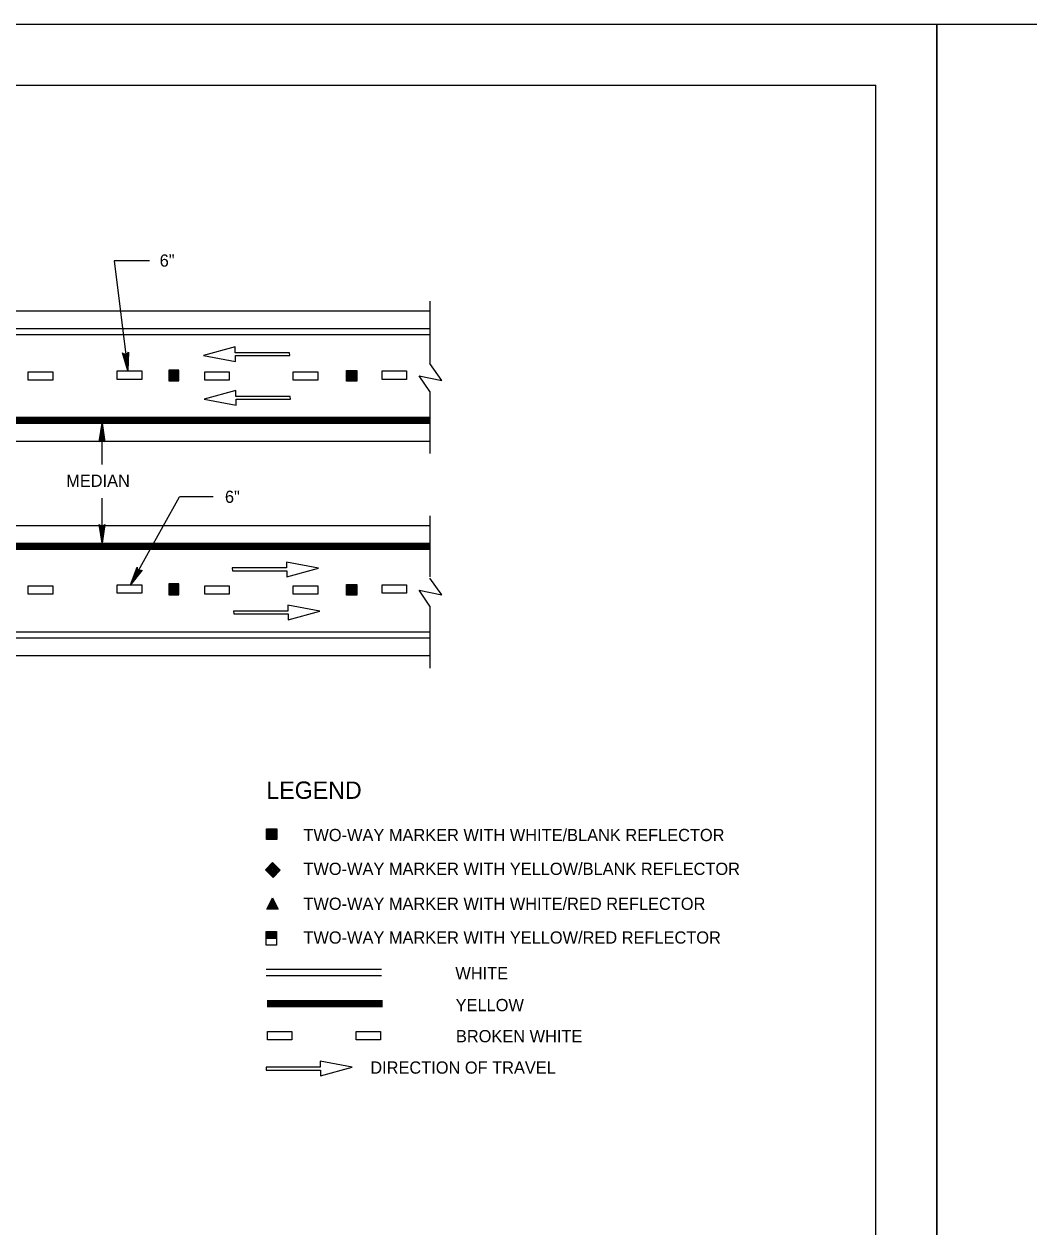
# Model space of a CAD drawing. Extents: x 639362 to 641108, y 298458 to 299646.
# Drawn here: x 639979.6 to 640225.9, y 299350.7 to 299645.6 of the extents above; entities that cross this region are included whole.
import ezdxf

# ---------------------------------------------------------------- set-up
doc = ezdxf.new("R2010")
doc.units = 0
for name, color, linetype in [('1', 7, 'Continuous'), ('2', 7, 'Continuous'), ('PLT-BNDY', 7, 'Continuous')]:
    doc.layers.add(name, color=color, linetype=linetype)

msp = doc.modelspace()

# ---------------------------------------------------------------- linework, layer by layer
at = {"layer": '1'}
for p in [(639402.31, 299630.63), (640188.31, 299066.63)]:
    msp.add_line(p, (640188.31, 299630.63), dxfattribs=at)
at = {"layer": '2'}
for p, q in [((640001.7, 299587.59), (640004.99, 299560.58)), ((640010.32, 299587.59), (640001.7, 299587.59)), ((640078.99, 299577.68), (640078.99, 299562.41)), ((639844.48, 299575.33), (640078.99, 299575.33)), ((639844.48, 299570.98), (640078.99, 299570.98)), ((639844.48, 299569.48), (640078.99, 299569.48)), ((640031.32, 299566.5), (640023.59, 299564.39)), ((640023.59, 299564.39), (640031.4, 299562.91)), ((640031.32, 299565.06), (640031.32, 299566.5)), ((640044.64, 299565.06), (640031.32, 299565.06)), ((640031.4, 299562.91), (640031.4, 299564.35)), ((640031.4, 299564.35), (640044.72, 299564.35)), ((640044.72, 299564.39), (640044.64, 299565.06)), ((640044.72, 299564.35), (640044.72, 299564.39)), ((640081.94, 299558.27), (640078.99, 299562.41)), ((639980.6, 299558.33), (639980.6, 299560.39)), ((639980.6, 299560.39), (639986.61, 299560.39)), ((639986.61, 299558.33), (639980.6, 299558.33)), ((639986.61, 299560.39), (639986.61, 299558.33)), ((640002.41, 299558.51), (640002.41, 299560.58)), ((640002.41, 299560.58), (640008.42, 299560.58)), ((640008.42, 299558.51), (640002.41, 299558.51)), ((640008.42, 299560.58), (640008.42, 299558.51)), ((640017.55, 299560.81), (640015.05, 299560.81)), ((640015.05, 299560.81), (640015.05, 299558.16)), ((640015.05, 299558.16), (640017.55, 299558.16)), ((640017.36, 299560.68), (640015.23, 299560.68)), ((640015.23, 299560.68), (640015.23, 299558.29)), ((640015.23, 299558.29), (640017.36, 299558.29)), ((640017.18, 299560.51), (640015.41, 299560.51)), ((640015.41, 299560.51), (640015.41, 299558.47)), ((640015.41, 299558.47), (640017.18, 299558.47)), ((640017, 299560.33), (640015.59, 299560.33)), ((640015.59, 299560.33), (640015.59, 299558.64)), ((640015.59, 299558.64), (640017, 299558.64)), ((640016.83, 299560.15), (640015.76, 299560.15)), ((640015.76, 299560.15), (640015.76, 299558.82)), ((640015.76, 299558.82), (640016.83, 299558.82)), ((640015.94, 299559.97), (640015.94, 299559)), ((640016.65, 299559.97), (640015.94, 299559.97)), ((640015.94, 299559), (640016.65, 299559)), ((640016.47, 299559.79), (640016.12, 299559.79)), ((640016.12, 299559.79), (640016.12, 299559.17)), ((640016.12, 299559.17), (640016.47, 299559.17)), ((640016.3, 299559.62), (640016.3, 299559.35)), ((640016.47, 299559.17), (640016.47, 299559.79)), ((640016.65, 299559), (640016.65, 299559.97)), ((640016.83, 299558.82), (640016.83, 299560.15)), ((640017, 299558.64), (640017, 299560.33)), ((640017.18, 299558.47), (640017.18, 299560.51)), ((640017.36, 299558.29), (640017.36, 299560.68)), ((640017.55, 299558.16), (640017.55, 299560.81)), ((640023.86, 299558.33), (640023.86, 299560.39)), ((640023.86, 299560.39), (640029.87, 299560.39)), ((640029.87, 299558.33), (640023.86, 299558.33)), ((640029.87, 299560.39), (640029.87, 299558.33)), ((640045.56, 299558.33), (640045.56, 299560.39)), ((640045.56, 299560.39), (640051.57, 299560.39)), ((640051.57, 299558.33), (640045.56, 299558.33)), ((640051.57, 299560.39), (640051.57, 299558.33)), ((640058.61, 299560.69), (640061.1, 299560.69)), ((640058.61, 299558.04), (640058.61, 299560.69)), ((640061.1, 299558.04), (640058.61, 299558.04)), ((640058.79, 299560.56), (640060.92, 299560.56)), ((640058.79, 299558.17), (640058.79, 299560.56)), ((640060.92, 299558.17), (640058.79, 299558.17)), ((640058.97, 299560.38), (640060.75, 299560.38)), ((640058.97, 299558.35), (640058.97, 299560.38)), ((640060.75, 299558.35), (640058.97, 299558.35)), ((640059.15, 299560.21), (640060.57, 299560.21)), ((640059.15, 299558.52), (640059.15, 299560.21)), ((640060.57, 299558.52), (640059.15, 299558.52)), ((640059.33, 299560.03), (640060.39, 299560.03)), ((640059.33, 299558.7), (640059.33, 299560.03)), ((640060.39, 299558.7), (640059.33, 299558.7)), ((640059.5, 299558.88), (640059.5, 299559.85)), ((640059.5, 299559.85), (640060.21, 299559.85)), ((640060.21, 299558.88), (640059.5, 299558.88)), ((640059.68, 299559.68), (640060.04, 299559.68)), ((640059.68, 299559.05), (640059.68, 299559.68)), ((640060.04, 299559.05), (640059.68, 299559.05)), ((640059.86, 299559.5), (640059.86, 299559.23)), ((640060.04, 299559.68), (640060.04, 299559.05)), ((640060.21, 299559.85), (640060.21, 299558.88)), ((640060.39, 299560.03), (640060.39, 299558.7)), ((640060.57, 299560.21), (640060.57, 299558.52)), ((640060.75, 299560.38), (640060.75, 299558.35)), ((640060.92, 299560.56), (640060.92, 299558.17)), ((640061.1, 299560.69), (640061.1, 299558.04)), ((640067.32, 299558.51), (640067.32, 299560.58)), ((640067.32, 299560.58), (640073.34, 299560.58)), ((640073.34, 299558.51), (640067.32, 299558.51)), ((640073.34, 299560.58), (640073.34, 299558.51)), ((640078.99, 299555.54), (640076.41, 299559.41)), ((640076.41, 299559.41), (640081.94, 299558.27)), ((640031.47, 299555.79), (640023.75, 299553.68)), ((640031.47, 299554.35), (640031.47, 299555.79)), ((640078.99, 299555.54), (640078.99, 299540.35)), ((640023.75, 299553.68), (640031.55, 299552.2)), ((640044.8, 299554.35), (640031.47, 299554.35)), ((640031.55, 299552.2), (640031.55, 299553.64)), ((640031.55, 299553.64), (640044.88, 299553.64)), ((640044.88, 299553.68), (640044.8, 299554.35)), ((640044.88, 299553.64), (640044.88, 299553.68)), ((639844.48, 299549.24), (640078.99, 299549.24)), ((639844.48, 299549.09), (640078.99, 299549.09)), ((639844.48, 299548.94), (640078.99, 299548.94)), ((639844.48, 299548.79), (640078.99, 299548.79)), ((639844.48, 299548.64), (640078.99, 299548.64)), ((639844.48, 299548.49), (640078.99, 299548.49)), ((639844.48, 299548.34), (640078.99, 299548.34)), ((639844.48, 299548.19), (640078.99, 299548.19)), ((639844.48, 299548.04), (640078.99, 299548.04)), ((639844.48, 299547.89), (640078.99, 299547.89)), ((639844.48, 299547.74), (640078.99, 299547.74)), ((639998.69, 299537.63), (639998.69, 299547.74)), ((639844.48, 299543.39), (640078.99, 299543.39)), ((639998.69, 299518.37), (639998.69, 299529.4)), ((640005.71, 299508.13), (640017.67, 299529.74)), ((640025.91, 299529.74), (640017.67, 299529.74)), ((639844.48, 299522.72), (640078.99, 299522.72)), ((640078.99, 299525.08), (640078.99, 299510.14)), ((639844.48, 299518.37), (640078.99, 299518.37)), ((639844.48, 299518.22), (640078.99, 299518.22)), ((639844.48, 299518.07), (640078.99, 299518.07)), ((639844.48, 299517.92), (640078.99, 299517.92)), ((639844.48, 299517.77), (640078.99, 299517.77)), ((639844.48, 299517.62), (640078.99, 299517.62)), ((639844.48, 299517.47), (640078.99, 299517.47)), ((639844.48, 299517.32), (640078.99, 299517.32)), ((639844.48, 299517.17), (640078.99, 299517.17)), ((639844.48, 299517.02), (640078.99, 299517.02)), ((639844.48, 299516.87), (640078.99, 299516.87)), ((640030.6, 299512.28), (640030.6, 299512.25)), ((640043.93, 299512.28), (640030.6, 299512.28)), ((640030.6, 299512.25), (640030.68, 299511.58)), ((640030.68, 299511.58), (640044.01, 299511.58)), ((640051.73, 299512.25), (640043.93, 299513.73)), ((640043.93, 299513.73), (640043.93, 299512.28)), ((640044.01, 299510.13), (640051.73, 299512.25)), ((640044.01, 299511.58), (640044.01, 299510.13)), ((639980.6, 299505.88), (639980.6, 299507.94)), ((639980.6, 299507.94), (639986.61, 299507.94)), ((639986.61, 299507.94), (639986.61, 299505.88)), ((640002.41, 299506.07), (640002.41, 299508.13)), ((640002.41, 299508.13), (640008.42, 299508.13)), ((640008.42, 299508.13), (640008.42, 299506.07)), ((640017.55, 299508.37), (640015.05, 299508.37)), ((640015.05, 299508.37), (640015.05, 299505.71)), ((640017.36, 299508.24), (640015.23, 299508.24)), ((640015.23, 299508.24), (640015.23, 299505.84)), ((640017.18, 299508.06), (640015.41, 299508.06)), ((640015.41, 299508.06), (640015.41, 299506.02)), ((640017, 299507.88), (640015.59, 299507.88)), ((640015.59, 299507.88), (640015.59, 299506.2)), ((640017, 299506.2), (640017, 299507.88)), ((640017.18, 299506.02), (640017.18, 299508.06)), ((640017.36, 299505.84), (640017.36, 299508.24)), ((640017.55, 299505.71), (640017.55, 299508.37)), ((640023.86, 299505.88), (640023.86, 299507.94)), ((640023.86, 299507.94), (640029.87, 299507.94)), ((640029.87, 299507.94), (640029.87, 299505.88)), ((640045.56, 299505.88), (640045.56, 299507.94)), ((640045.56, 299507.94), (640051.57, 299507.94)), ((640051.57, 299507.94), (640051.57, 299505.88)), ((640058.61, 299508.25), (640061.1, 299508.25)), ((640058.61, 299505.6), (640058.61, 299508.25)), ((640058.79, 299508.12), (640060.92, 299508.12)), ((640058.79, 299505.72), (640058.79, 299508.12)), ((640058.97, 299507.94), (640060.75, 299507.94)), ((640058.97, 299505.9), (640058.97, 299507.94)), ((640060.75, 299507.94), (640060.75, 299505.9)), ((640060.92, 299508.12), (640060.92, 299505.72)), ((640061.1, 299508.25), (640061.1, 299505.6)), ((640067.32, 299506.07), (640067.32, 299508.13)), ((640067.32, 299508.13), (640073.34, 299508.13)), ((640073.34, 299508.13), (640073.34, 299506.07)), ((640081.94, 299505.67), (640078.99, 299509.8)), ((639986.61, 299505.88), (639980.6, 299505.88)), ((640008.42, 299506.07), (640002.41, 299506.07)), ((640015.05, 299505.71), (640017.55, 299505.71)), ((640015.23, 299505.84), (640017.36, 299505.84)), ((640015.41, 299506.02), (640017.18, 299506.02)), ((640015.59, 299506.2), (640017, 299506.2)), ((640016.83, 299507.7), (640015.76, 299507.7)), ((640015.76, 299507.7), (640015.76, 299506.37)), ((640015.76, 299506.37), (640016.83, 299506.37)), ((640015.94, 299507.53), (640015.94, 299506.55)), ((640016.65, 299507.53), (640015.94, 299507.53)), ((640015.94, 299506.55), (640016.65, 299506.55)), ((640016.47, 299507.35), (640016.12, 299507.35)), ((640016.12, 299507.35), (640016.12, 299506.73)), ((640016.12, 299506.73), (640016.47, 299506.73)), ((640016.3, 299507.17), (640016.3, 299506.91)), ((640016.47, 299506.73), (640016.47, 299507.35)), ((640016.65, 299506.55), (640016.65, 299507.53)), ((640016.83, 299506.37), (640016.83, 299507.7)), ((640029.87, 299505.88), (640023.86, 299505.88)), ((640051.57, 299505.88), (640045.56, 299505.88)), ((640061.1, 299505.6), (640058.61, 299505.6)), ((640060.92, 299505.72), (640058.79, 299505.72)), ((640060.75, 299505.9), (640058.97, 299505.9)), ((640059.15, 299507.76), (640060.57, 299507.76)), ((640059.15, 299506.08), (640059.15, 299507.76)), ((640060.57, 299506.08), (640059.15, 299506.08)), ((640059.33, 299507.58), (640060.39, 299507.58)), ((640059.33, 299506.26), (640059.33, 299507.58)), ((640060.39, 299506.26), (640059.33, 299506.26)), ((640059.5, 299506.43), (640059.5, 299507.41)), ((640059.5, 299507.41), (640060.21, 299507.41)), ((640060.21, 299506.43), (640059.5, 299506.43)), ((640059.68, 299507.23), (640060.04, 299507.23)), ((640059.68, 299506.61), (640059.68, 299507.23)), ((640060.04, 299506.61), (640059.68, 299506.61)), ((640059.86, 299507.05), (640059.86, 299506.79)), ((640060.04, 299507.23), (640060.04, 299506.61)), ((640060.21, 299507.41), (640060.21, 299506.43)), ((640060.39, 299507.58), (640060.39, 299506.26)), ((640060.57, 299507.76), (640060.57, 299506.08)), ((640073.34, 299506.07), (640067.32, 299506.07)), ((640078.99, 299502.93), (640076.41, 299506.8)), ((640076.41, 299506.8), (640081.94, 299505.67)), ((640052.04, 299501.69), (640044.24, 299503.16)), ((640044.24, 299503.16), (640044.24, 299501.72)), ((640078.99, 299502.93), (640078.99, 299487.75)), ((640030.91, 299501.72), (640030.91, 299501.69)), ((640044.24, 299501.72), (640030.91, 299501.72)), ((640030.91, 299501.69), (640030.99, 299501.01)), ((640030.99, 299501.01), (640044.32, 299501.01)), ((640044.32, 299499.57), (640052.04, 299501.69)), ((640044.32, 299501.01), (640044.32, 299499.57)), ((639844.48, 299496.64), (640078.99, 299496.64)), ((639844.48, 299495.14), (640078.99, 299495.14)), ((639844.48, 299490.79), (640078.99, 299490.79)), ((640039.01, 299448.36), (640041.51, 299448.36)), ((640039.01, 299445.71), (640039.01, 299448.36)), ((640039.2, 299448.23), (640041.33, 299448.23)), ((640039.2, 299445.84), (640039.2, 299448.23)), ((640039.38, 299448.05), (640041.15, 299448.05)), ((640039.38, 299446.02), (640039.38, 299448.05)), ((640041.15, 299446.02), (640039.38, 299446.02)), ((640039.55, 299447.88), (640040.97, 299447.88)), ((640039.55, 299446.19), (640039.55, 299447.88)), ((640040.97, 299446.19), (640039.55, 299446.19)), ((640039.73, 299447.7), (640040.8, 299447.7)), ((640039.73, 299446.37), (640039.73, 299447.7)), ((640040.8, 299446.37), (640039.73, 299446.37)), ((640039.91, 299446.55), (640039.91, 299447.52)), ((640039.91, 299447.52), (640040.62, 299447.52)), ((640040.62, 299446.55), (640039.91, 299446.55)), ((640040.09, 299447.35), (640040.44, 299447.35)), ((640040.09, 299446.72), (640040.09, 299447.35)), ((640040.44, 299446.72), (640040.09, 299446.72)), ((640040.26, 299447.17), (640040.26, 299446.9)), ((640040.44, 299447.35), (640040.44, 299446.72)), ((640040.62, 299447.52), (640040.62, 299446.55)), ((640040.8, 299447.7), (640040.8, 299446.37)), ((640040.97, 299447.88), (640040.97, 299446.19)), ((640041.15, 299448.05), (640041.15, 299446.02)), ((640041.33, 299448.23), (640041.33, 299445.84)), ((640041.51, 299448.36), (640041.51, 299445.71)), ((640041.51, 299445.71), (640039.01, 299445.71)), ((640041.33, 299445.84), (640039.2, 299445.84)), ((640038.73, 299438.3), (640040.5, 299440.07)), ((640040.5, 299440.07), (640042.37, 299438.19)), ((640040.61, 299436.42), (640038.73, 299438.3)), ((640038.96, 299438.34), (640040.46, 299439.84)), ((640040.65, 299436.64), (640038.96, 299438.34)), ((640039.21, 299438.34), (640040.46, 299439.59)), ((640040.65, 299436.9), (640039.21, 299438.34)), ((640039.46, 299438.34), (640040.46, 299439.34)), ((640040.65, 299437.15), (640039.46, 299438.34)), ((640039.71, 299438.34), (640040.46, 299439.09)), ((640040.65, 299437.4), (640039.71, 299438.34)), ((640039.96, 299438.34), (640040.46, 299438.84)), ((640040.65, 299437.65), (640039.96, 299438.34)), ((640040.21, 299438.34), (640040.46, 299438.59)), ((640040.65, 299437.9), (640040.21, 299438.34)), ((640040.46, 299439.84), (640042.15, 299438.15)), ((640040.46, 299439.59), (640041.91, 299438.15)), ((640040.46, 299439.34), (640041.65, 299438.15)), ((640040.46, 299439.09), (640041.4, 299438.15)), ((640040.46, 299438.84), (640041.15, 299438.15)), ((640040.46, 299438.59), (640040.9, 299438.15)), ((640040.46, 299438.34), (640040.65, 299438.15)), ((640042.37, 299438.19), (640040.61, 299436.42)), ((640042.15, 299438.15), (640040.65, 299436.64)), ((640041.91, 299438.15), (640040.65, 299436.9)), ((640041.65, 299438.15), (640040.65, 299437.15)), ((640041.4, 299438.15), (640040.65, 299437.4)), ((640041.15, 299438.15), (640040.65, 299437.65)), ((640040.9, 299438.15), (640040.65, 299437.9)), ((640039.08, 299428.67), (640040.47, 299431.44)), ((640039.24, 299428.76), (640040.47, 299431.22)), ((640040.47, 299431.44), (640041.86, 299428.66)), ((640040.47, 299431.22), (640041.7, 299428.76)), ((640041.86, 299428.66), (640039.08, 299428.67)), ((640041.7, 299428.76), (640039.24, 299428.76)), ((640039.4, 299428.86), (640040.47, 299431)), ((640041.54, 299428.86), (640039.4, 299428.86)), ((640039.56, 299428.96), (640040.47, 299430.78)), ((640041.38, 299428.96), (640039.56, 299428.96)), ((640039.72, 299429.06), (640040.48, 299430.55)), ((640041.22, 299429.06), (640039.72, 299429.06)), ((640039.88, 299429.16), (640040.47, 299430.34)), ((640041.06, 299429.16), (640039.88, 299429.16)), ((640040.04, 299429.26), (640040.47, 299430.11)), ((640040.9, 299429.26), (640040.04, 299429.26)), ((640040.2, 299429.36), (640040.47, 299429.89)), ((640040.74, 299429.36), (640040.2, 299429.36)), ((640040.36, 299429.46), (640040.47, 299429.67)), ((640040.58, 299429.46), (640040.36, 299429.46)), ((640040.47, 299431), (640041.54, 299428.86)), ((640040.47, 299430.78), (640041.38, 299428.96)), ((640040.47, 299430.34), (640041.06, 299429.16)), ((640040.47, 299430.11), (640040.9, 299429.26)), ((640040.47, 299429.89), (640040.74, 299429.36)), ((640040.47, 299429.67), (640040.58, 299429.46)), ((640040.48, 299430.55), (640041.22, 299429.06)), ((640038.95, 299423.19), (640041.45, 299423.19)), ((640038.95, 299421.49), (640038.95, 299423.19)), ((640039.14, 299423.11), (640041.27, 299423.11)), ((640039.14, 299421.57), (640039.14, 299423.11)), ((640039.32, 299422.99), (640041.09, 299422.99)), ((640039.32, 299421.69), (640039.32, 299422.99)), ((640039.49, 299422.88), (640040.91, 299422.88)), ((640039.49, 299421.8), (640039.49, 299422.88)), ((640039.67, 299422.76), (640040.74, 299422.76)), ((640039.67, 299421.91), (640039.67, 299422.76)), ((640039.85, 299422.03), (640039.85, 299422.65)), ((640039.85, 299422.65), (640040.56, 299422.65)), ((640040.03, 299422.54), (640040.38, 299422.54)), ((640040.03, 299422.14), (640040.03, 299422.54)), ((640040.2, 299422.43), (640040.2, 299422.25)), ((640040.38, 299422.54), (640040.38, 299422.14)), ((640040.56, 299422.65), (640040.56, 299422.03)), ((640040.74, 299422.76), (640040.74, 299421.91)), ((640040.91, 299422.88), (640040.91, 299421.8)), ((640041.09, 299422.99), (640041.09, 299421.69)), ((640041.27, 299423.11), (640041.27, 299421.57)), ((640041.45, 299423.19), (640041.45, 299421.49)), ((640041.45, 299421.49), (640038.95, 299421.49)), ((640041.27, 299421.57), (640039.14, 299421.57)), ((640041.09, 299421.69), (640039.32, 299421.69)), ((640040.91, 299421.8), (640039.49, 299421.8)), ((640040.74, 299421.91), (640039.67, 299421.91)), ((640040.56, 299422.03), (640039.85, 299422.03)), ((640040.38, 299422.14), (640040.03, 299422.14)), ((640067.17, 299413.8), (640038.88, 299413.8)), ((640067.17, 299412.3), (640038.88, 299412.3)), ((640067.46, 299406.18), (640039.18, 299406.18)), ((640067.46, 299406.03), (640039.18, 299406.03)), ((640067.46, 299405.88), (640039.18, 299405.88)), ((640067.46, 299405.73), (640039.18, 299405.73)), ((640067.46, 299405.58), (640039.18, 299405.58)), ((640067.46, 299405.43), (640039.18, 299405.43)), ((640067.46, 299405.28), (640039.18, 299405.28)), ((640067.46, 299405.13), (640039.18, 299405.13)), ((640067.46, 299404.98), (640039.18, 299404.98)), ((640067.46, 299404.83), (640039.18, 299404.83)), ((640067.46, 299404.68), (640039.18, 299404.68)), ((640039.24, 299396.59), (640039.24, 299398.66)), ((640039.24, 299398.66), (640045.25, 299398.66)), ((640045.25, 299396.59), (640039.24, 299396.59)), ((640045.25, 299398.66), (640045.25, 299396.59)), ((640060.94, 299396.59), (640060.94, 299398.66)), ((640060.94, 299398.66), (640066.95, 299398.66)), ((640066.95, 299396.59), (640060.94, 299396.59)), ((640066.95, 299398.66), (640066.95, 299396.59)), ((640052.16, 299389.9), (640038.91, 299389.9)), ((640038.91, 299389.9), (640038.91, 299389.2)), ((640059.96, 299389.87), (640052.16, 299391.34)), ((640052.16, 299391.34), (640052.16, 299389.9)), ((640038.91, 299389.2), (640052.24, 299389.2)), ((640052.24, 299387.75), (640059.96, 299389.87)), ((640052.24, 299389.2), (640052.24, 299387.75))]:
    msp.add_line(p, q, dxfattribs=at)
for points in [[(640005.01, 299564.93), (640004.72, 299564.74), (640004.99, 299560.58), (640005.01, 299564.93), (640005.17, 299565.17), (640004.99, 299560.58), (640004.29, 299564.68), (640003.96, 299564.79), (640004.99, 299560.58), (640003.73, 299565), (640003.96, 299564.79)], [(639998.14, 299543.42), (639998.45, 299543.58), (639998.69, 299547.74), (639998.14, 299543.42), (639997.95, 299543.2), (639998.69, 299547.74), (639998.89, 299543.59), (639999.2, 299543.44), (639998.69, 299547.74), (639999.4, 299543.2), (639999.2, 299543.44)], [(639999.23, 299522.69), (639998.92, 299522.53), (639998.69, 299518.37), (639999.23, 299522.69), (639999.42, 299522.91), (639998.69, 299518.37), (639998.48, 299522.53), (639998.17, 299522.68), (639998.69, 299518.37), (639997.97, 299522.91), (639998.17, 299522.68)], [(640008.27, 299511.65), (640007.92, 299511.66), (640005.71, 299508.13), (640008.27, 299511.65), (640008.55, 299511.75), (640005.71, 299508.13), (640007.54, 299511.86), (640007.34, 299512.15), (640005.71, 299508.13), (640007.28, 299512.45), (640007.34, 299512.15)]]:
    msp.add_lwpolyline(points, dxfattribs=at)
msp.add_lwpolyline([(640038.95, 299421.49), (640041.45, 299421.49), (640041.45, 299419.8), (640038.95, 299419.8)], close=True, dxfattribs=at)
at = {"layer": 'PLT-BNDY'}
for points in [[(639362.31, 299645.63), (640203.31, 299645.63), (640203.31, 299051.63), (639362.31, 299051.63)], [(640203.31, 299645.63), (641044.31, 299645.63), (641044.31, 299051.63), (640203.31, 299051.63)]]:
    msp.add_lwpolyline(points, close=True, dxfattribs=at)

# ---------------------------------------------------------------- texts
at = {"layer": '2'}
for s, height, p in [('6"', 3, (640012.82, 299586.15)), ('MEDIAN', 3, (639989.91, 299532.16)), ('6"', 3, (640028.82, 299528.23)), ('LEGEND', 4.25, (640038.96, 299455.68)), ('TWO-WAY MARKER WITH WHITE/BLANK REFLECTOR', 3, (640048.05, 299445.31)), ('TWO-WAY MARKER WITH YELLOW/BLANK REFLECTOR', 3, (640048.05, 299437.02)), ('TWO-WAY MARKER WITH WHITE/RED REFLECTOR', 3, (640048.05, 299428.46)), ('TWO-WAY MARKER WITH YELLOW/RED REFLECTOR', 3, (640048.05, 299420.18)), ('WHITE', 3, (640085.29, 299411.42)), ('YELLOW', 3, (640085.36, 299403.62)), ('BROKEN WHITE', 3, (640085.43, 299396)), ('DIRECTION OF TRAVEL', 3, (640064.44, 299388.3))]:
    msp.add_text(s, height=height, dxfattribs=at).set_placement(p)

doc.saveas('drawing.dxf')
